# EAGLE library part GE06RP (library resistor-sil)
SIL RESISTOR
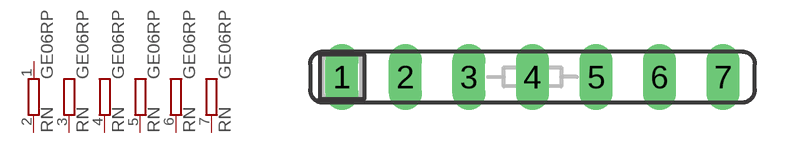
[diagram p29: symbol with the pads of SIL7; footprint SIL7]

Designator prefix RN; gates A=R-PV B=R-PV1 C=R-PV1 D=R-PV1 E=R-PV1 F=R-PV1

## GE06RP (OC_FARNELL: unknown; OC_NEWARK: unknown)  [SIL7]
1  A:1  pas
2  A:2  pas
3  B:2  pas
4  C:2  pas
5  D:2  pas
6  E:2  pas
7  F:2  pas

## Footprint SIL7 (pad centres in mm)
Single In Line
drill 0.813 long: 1 -7.62,0; 2 -5.08,0; 3 -2.54,0; 4 0,0; 5 2.54,0; 6 5.08,0; 7 7.62,0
